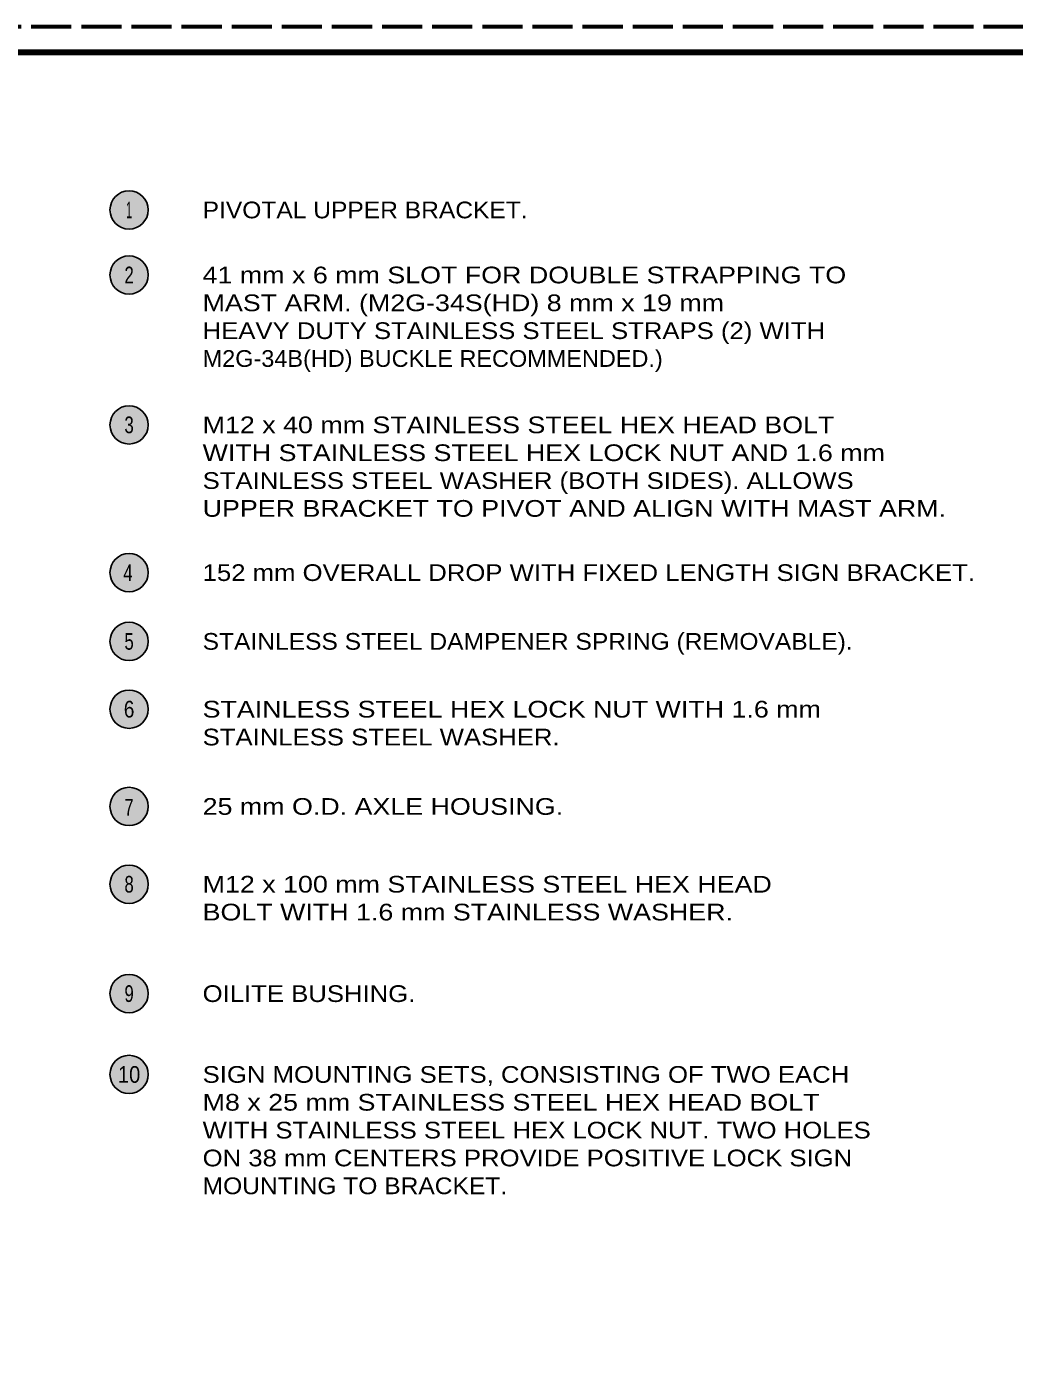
# Model space of a CAD drawing. Extents: x 312583 to 312853, y 144376 to 144586.
# Drawn here: x 312681 to 312725.3, y 144525.9 to 144586.2 of the extents above; entities that cross this region are included whole.
import ezdxf
from ezdxf.enums import TextEntityAlignment as Align

# ---------------------------------------------------------------- set-up
doc = ezdxf.new("R2010")
doc.units = 0
doc.header["$LTSCALE"] = 0.3
doc.linetypes.add('LONG_DASHED', pattern=[7.5, 6, -1.5])
for name, color, linetype, lineweight in [('1', 7, 'Continuous', 25), ('2', 7, 'Continuous', 13), ('63', 7, 'LONG_DASHED', 60)]:
    doc.layers.add(name, color=color, linetype=linetype, lineweight=lineweight)

msp = doc.modelspace()

# ---------------------------------------------------------------- hatches: boundary and pattern name
at = {"layer": '2'}
for points in [[(312686.4534, 144578.006, 1), (312684.7342, 144578.006, 1)], [(312686.4534, 144575.0869, 1), (312684.7342, 144575.0869, 1)], [(312686.4534, 144568.3573, 1), (312684.7342, 144568.3573, 1)], [(312686.4534, 144561.7248, 1), (312684.7342, 144561.7248, 1)], [(312686.4534, 144558.6377, 1), (312684.7342, 144558.6377, 1)], [(312686.4534, 144555.5933, 1), (312684.7342, 144555.5933, 1)], [(312686.4534, 144551.2266, 1), (312684.7342, 144551.2266, 1)], [(312686.4534, 144547.7351, 1), (312684.7342, 144547.7351, 1)], [(312686.4534, 144542.8246, 1), (312684.7342, 144542.8246, 1)], [(312686.4534, 144539.1962, 1), (312684.7342, 144539.1962, 1)]]:
    msp.add_hatch(color=256, dxfattribs=at).paths.add_polyline_path(points)

# ---------------------------------------------------------------- linework, layer by layer
at = {"layer": '1', "lineweight": 158}
msp.add_lwpolyline([(312616.5, 144423.1446), (312616.5, 144585.0846), (312849, 144585.0846)], dxfattribs=at)
at = {"layer": '2', "lineweight": 25}
for centre in [(312685.5938, 144578.006), (312685.5938, 144575.0869), (312685.5938, 144568.3573), (312685.5938, 144561.7248), (312685.5938, 144558.6377), (312685.5938, 144555.5933), (312685.5938, 144551.2266), (312685.5938, 144547.7351), (312685.5938, 144542.8246), (312685.5938, 144539.1962)]:
    msp.add_circle(centre, 0.8596, dxfattribs=at)
at = {"layer": '63'}
msp.add_line((312851.75, 144586.2246), (312583.526, 144586.2246), dxfattribs=at)

# ---------------------------------------------------------------- texts
at = {"layer": '2'}
for s, width, p in [('1', 0.5, (312685.5938, 144577.631)), ('2', 0.75, (312685.5938, 144574.7119)), ('3', 0.75, (312685.5938, 144567.9823)), ('4', 0.75, (312685.5431, 144561.3427)), ('5', 0.75, (312685.5938, 144558.2627)), ('6', 0.85, (312685.5938, 144555.2183)), ('7', 0.75, (312685.5879, 144550.8164)), ('8', 0.75, (312685.5938, 144547.3601)), ('9', 0.75, (312685.5938, 144542.4496)), ('10', 0.9, (312685.5938, 144538.8212))]:
    msp.add_text(s, height=0.75, dxfattribs=dict(at, width=width)).set_placement(p, align=Align.CENTER)
for s, width, p in [('PIVOTAL UPPER BRACKET.', 1.1, (312688.8942, 144577.631)), ('41 mm x 6 mm SLOT FOR DOUBLE STRAPPING TO', 1.2, (312688.8942, 144574.7119)), ('MAST ARM. (M2G-34S(HD) 8 mm x 19 mm', 1.2, (312688.8942, 144573.4619)), ('HEAVY DUTY STAINLESS STEEL STRAPS (2) WITH', 1.15, (312688.8942, 144572.2119)), ('M2G-34B(HD) BUCKLE RECOMMENDED.)', 1.05, (312688.8942, 144570.9619)), ('M12 x 40 mm STAINLESS STEEL HEX HEAD BOLT', 1.2, (312688.8942, 144567.9823)), ('WITH STAINLESS STEEL HEX LOCK NUT AND 1.6 mm', 1.2, (312688.8942, 144566.7323)), ('STAINLESS STEEL WASHER (BOTH SIDES). ALLOWS', 1.15, (312688.8942, 144565.4823)), ('UPPER BRACKET TO PIVOT AND ALIGN WITH MAST ARM.', 1.2, (312688.8942, 144564.2323)), ('152 mm OVERALL DROP WITH FIXED LENGTH SIGN BRACKET.', 1.15, (312688.8942, 144561.3498)), ('STAINLESS STEEL DAMPENER SPRING (REMOVABLE).', 1.1, (312688.8942, 144558.2627)), ('STAINLESS STEEL HEX LOCK NUT WITH 1.6 mm', 1.2, (312688.8942, 144555.2183)), ('STAINLESS STEEL WASHER. ', 1.15, (312688.8942, 144553.9683)), ('25 mm O.D. AXLE HOUSING.', 1.2, (312688.8942, 144550.8516)), ('M12 x 100 mm STAINLESS STEEL HEX HEAD', 1.2, (312688.8942, 144547.3601)), ('BOLT WITH 1.6 mm STAINLESS WASHER.', 1.2, (312688.8942, 144546.1101)), ('OILITE BUSHING.', 1.15, (312688.8942, 144542.4496)), ('SIGN MOUNTING SETS, CONSISTING OF TWO EACH', 1.15, (312688.8942, 144538.8212)), ('M8 x 25 mm STAINLESS STEEL HEX HEAD BOLT', 1.2, (312688.8942, 144537.5712)), ('WITH STAINLESS STEEL HEX LOCK NUT. TWO HOLES', 1.15, (312688.8942, 144536.3212)), ('ON 38 mm CENTERS PROVIDE POSITIVE LOCK SIGN', 1.15, (312688.8942, 144535.0712)), ('MOUNTING TO BRACKET.', 1.1, (312688.8942, 144533.8212))]:
    msp.add_text(s, height=0.75, dxfattribs=dict(at, width=width)).set_placement(p)

doc.saveas('drawing.dxf')
